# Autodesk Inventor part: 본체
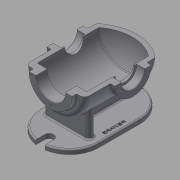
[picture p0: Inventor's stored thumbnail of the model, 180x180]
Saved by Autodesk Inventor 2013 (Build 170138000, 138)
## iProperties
Created: 2016-02
Part Number: 본체
Material: 일반
Document SubType Name: Modeling
Designer: mduedu
Density: 2.71 g/cm^3
Author: mduedu
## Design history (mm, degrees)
sketch "스케치2"
  geometry: L1 (0, 90)-(0, -90); L2 (65, -65.993)-(65, 90); L3 (65, 90)-(0, 90); A1 r 100 centre (0, 10) between (0, -90) and (65, -65.993); 2 further points
  constraints: 6 end point, 2 point on circle, 1 centre point, 1 coincident, 1 horizontal, 1 midpoint, 1 parallel, 1 point on line, 1 vertical
  dimensions: "d3" = 180 distance of L1.start L1.end; "d5" = 130 diameter of L2 L1; "d6" = 100 radius of A1
revolve "회전1" sketch "스케치2" stored, may be unused: angle "d7" = 90 deg
sketch "스케치3"
  geometry: C1 r 47.5 at (0, 0); 1 further point
  constraints: 1 centre point, 1 coincident
  dimensions: "d8" = 95 diameter of C1
extrude "돌출2" join sketch "스케치3" distance "d10" = 10; taper "d11" = 0 deg
sketch "스케치5"
  geometry: L1 (47.5, 100)-(47.5, 90) reference; L2 (47.5, 90)-(65, 90) reference; L3 (65, 90)-(65, -65.993) reference; L4 (-65, -65.993)-(-65, 90) reference; L5 (-65, 90)-(-47.5, 90) reference; L6 (-47.5, 90)-(-47.5, 100) reference; L7 (-47.5, 100)-(47.5, 100) reference; L8 (55, 75)-(55, -61.239); L9 (0, 75)-(55, 75); L10 (0, 75)-(0, -80); A1 r 100 centre (0, 10) between (-65, -65.993) and (0, -90) reference; A2 r 100 centre (0, 10) between (0, -90) and (65, -65.993) reference; A3 r 90 centre (0, 10) between (0, -80) and (55, -61.239); 1 further point
  constraints: 6 end point, 2 point on circle, 1 centre point, 1 parallel, 1 perpendicular, 1 point on line, 1 vertical
  dimensions: "d13" = 10 distance between parallel lines of L3 L8; "d14" = 10 radial gap between concentric circles of A3 A1; "d15" = 15 distance between parallel lines of L9 L2
revolve "회전2" sketch "스케치5" stored, may be unused: angle "d16" = 90 deg
hole "구멍1" diameter "d19" = 65; stored, may be unused: countersink angle "d23" = 90 deg, drill point angle "d25" = 118 deg; dims "d17" = 10, "d18" = 10, "d20" = 6, "d21" = 4, "d22" = 2, "d24" = 8
node "작업 평면1"
sketch "스케치6"
  geometry: L1 (47.5, 100)-(-47.5, 100) reference; C1 r 40 at (0, -7); 1 further point
  constraints: 1 centre point, 1 vertical alignment
  dimensions: "d27" = 80 diameter of C1; "d29" = 107 distance from line of C1.centre L1
extrude "돌출3" join sketch "스케치6" stored distance "d30" = 10; taper "d31" = 0 deg
hole "구멍2" diameter "d34" = 42; stored, may be unused: countersink angle "d38" = 90 deg, drill point angle "d40" = 118 deg; dims "d32" = 10, "d33" = 10, "d35" = 6, "d36" = 52, "d37" = 18, "d39" = 8
sketch "스케치7" dims "d41" = 65
  geometry: C1 r 40 at (0, 0) reference; 3 further points
  constraints: 2 vertical alignment, 1 coincident, 2 other
hole "구멍3" sketch "스케치7" at (0, 32.5) diameter "d43" = 3.242; stored, may be unused: countersink angle "d47" = 90 deg, drill point angle "d49" = 118 deg; dims "d44" = 11, "d45" = 13, "d46" = 18, "d48" = 13
sketch "스케치8" dims "d53" = 80
  geometry: 3 further points
  constraints: 2 vertical alignment, 1 coincident, 2 other
hole "구멍4" sketch "스케치8" at (0, -40) diameter "d56" = 3.242; stored, may be unused: countersink angle "d60" = 90 deg, drill point angle "d62" = 118 deg; dims "d57" = 11, "d58" = 13, "d59" = 18, "d61" = 13
fillet "모깎기1" dims "d66" = 10
fillet "모깎기2" dims "d67" = 3
fillet "모깎기3" dims "d68" = 0.3
chamfer "모따기1" distance "d69" = 1; stored, may be unused: second distance "d70" = 2, angle "d71" = 45 deg
node "작업 평면5"
sketch "스케치10"
  geometry: L1 (-50, 66)-(50, 66); L2 (50, 66)-(50, 50); L3 (50, 50)-(-50, 50); L4 (-50, 50)-(-50, 66); 2 further points
  constraints: 8 end point, 2 horizontal, 2 vertical, 1 midpoint, 1 vertical alignment
  dimensions: "d177" = 50 distance from line of L3 point (0, 0); "d178" = 100 distance of L1.start L1.end; "d179" = 16 distance of L3.end L1.start
extrude "돌출5" join sketch "스케치10" stored distance "d84" = 10; taper "d85" = 0 deg
sketch "스케치21" dims "d180" = 220, "d182" = 130
  geometry: L1 (65, 58)-(-65, 58); L2 (-65, 58)-(-65, -32); L3 (-65, -32)-(65, -32); L4 (65, -32)-(65, 58); L5 (50, 50)-(50, 66) reference; 4 further points
  constraints: 8 end point, 3 horizontal alignment, 3 midpoint, 2 parallel, 1 horizontal, 1 perpendicular, 1 vertical alignment, 4 other
extrude "돌출13" join sketch "스케치21" distance "d183" = 10; taper "d184" = 0 deg
sketch "스케치11"
  geometry: L1 (-65, 80)-(-65, -61.239) reference; L2 (-100, -97)-(-100, -32) reference; L3 (-65, -42.793)-(-100, -63); L4 (-100, -97)-(-110, -97) reference; 1 further point
  constraints: 2 end point, 2 point on line
  dimensions: "d185" = 34 distance from line of L3.end L4; "d186" = 120 deg angle of L2 L3
feature "리브1" sketch "스케치11" dims "d88" = 1, "d89" = 16, "d90" = 0, "d91" = 0, "d92" = 1, "d93" = 1
fillet "모깎기12"
fillet "모깎기13"
fillet "모깎기16" dims "d167" = 3
fillet "모깎기18"
fillet "모깎기17" dims "d168" = 3
fillet "모깎기19" dims "d187" = 3
node "작업 평면6"
sketch "스케치19"
  geometry: L1 (75, -47)-(75, 33) reference; L2 (-75, -47)-(-75, 33) reference; L3 (75, -7)-(-75, -7); C1 r 22.5 at (0, -7); 1 further point
  constraints: 3 midpoint, 2 end point, 1 centre point
  dimensions: "d149" = 45 diameter of C1
extrude "돌출11" join sketch "스케치19" stored distance "d150" = 10; taper "d151" = 0 deg
hole "구멍6" diameter "d154" = 33.376; stored, may be unused: countersink angle "d158" = 90 deg, drill point angle "d160" = 118 deg; dims "d155" = 6, "d156" = 4, "d157" = 2, "d159" = 8, "d190" = 10, "d191" = 10
fillet "모깎기11" dims "d161" = 3
chamfer "모따기3" distance "d164" = 1; stored, may be unused: second distance "d165" = 2, angle "d166" = 45 deg
node "작업 평면9"
  node "작업 평면8"
sketch "스케치22" dims "d189" = 20
  geometry: L1 (-10, -123)-(10, -123); L2 (10, -123)-(10, -103); L3 (10, -103)-(-10, -103); L4 (-10, -103)-(-10, -123); A1 r 65 centre (0, -58) between (-65, -58) and (65, -58) reference; 2 further points
  constraints: 8 end point, 2 parallel, 1 horizontal, 1 horizontal alignment, 1 midpoint, 1 perpendicular, 1 tangent, 1 vertical alignment, 2 other
  dimensions: "d193" = 30 dimension on L1
extrude "돌출14" cut sketch "스케치22" stored distance "d194" = 10; taper "d195" = 0 deg
fillet "모깎기21" dims "d196" = 3
feature "분할1"
sketch "스케치23"
  geometry: L1 (-65, 32)-(-65, -58) reference; L2 (65, -58)-(65, 32) reference; L3 (-65, -13)-(65, -13); 2 further points
  constraints: 2 end point, 2 midpoint, 1 point on line, 1 other
  dimensions: "d197" = 12 distance from line of point (53, -13) L2
feature "엠보싱2" sketch "스케치23" dims "d8" = 95, "d198" = 0.5, "d199" = 0
node "솔리드2"
pattern_circular "원형 패턴1" dims angle "d51" = 360 deg
mirror "대칭1"
pattern_circular "원형 패턴2" dims angle "d64" = 360 deg
mirror "대칭3"
node "절단 모서리 투영1"
other parameters: "d26" = 75, "d136" = 175
